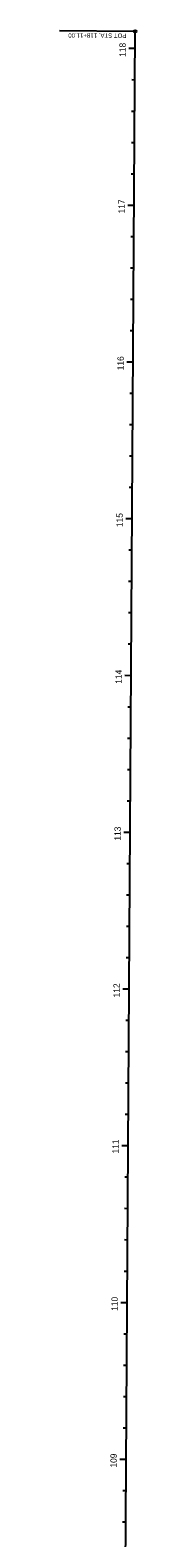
# Model space of a CAD drawing. Extents: x 509738 to 512118, y 1314883 to 1316817.
# Drawn here: x 510443 to 510492, y 1315855 to 1316817 of the extents above; entities that cross this region are included whole.
import ezdxf

# ---------------------------------------------------------------- set-up
doc = ezdxf.new("R2010")
doc.units = 0
for name, color, linetype in [('CLConst_dp', 7, 'Continuous'), ('CurveDataLabel_dp', 7, 'Continuous'), ('StationTicL_dp', 7, 'Continuous'), ('StationTicS_dp', 7, 'Continuous'), ('TextBLStation', 7, 'Continuous')]:
    doc.layers.add(name, color=color, linetype=linetype)

msp = doc.modelspace()

# ---------------------------------------------------------------- linework, layer by layer
at = {"layer": 'CLConst_dp'}
msp.add_line((510484.13, 1315694.91), (510491.26, 1316815.91), dxfattribs=at)
at = {"layer": 'CurveDataLabel_dp'}
msp.add_line((510490.46, 1316815.91), (510442.98, 1316816.21), dxfattribs=at)
msp.add_circle((510491.26, 1316815.91), 0.8, dxfattribs=at)
at = {"layer": 'StationTicL_dp'}
for p, q in [((510491.19, 1316804.91), (510487.19, 1316804.93)), ((510490.56, 1316704.91), (510486.56, 1316704.94)), ((510489.92, 1316604.91), (510485.92, 1316604.94)), ((510489.29, 1316504.91), (510485.29, 1316504.94)), ((510488.65, 1316404.92), (510484.65, 1316404.94)), ((510488.01, 1316304.92), (510484.01, 1316304.94)), ((510487.38, 1316204.92), (510483.38, 1316204.95)), ((510486.74, 1316104.92), (510482.74, 1316104.95)), ((510486.11, 1316004.92), (510482.11, 1316004.95)), ((510485.47, 1315904.93), (510481.47, 1315904.95))]:
    msp.add_line(p, q, dxfattribs=at)
at = {"layer": 'StationTicS_dp'}
for p, q in [((510491.07, 1316784.91), (510489.07, 1316784.92)), ((510490.94, 1316764.91), (510488.94, 1316764.92)), ((510490.81, 1316744.91), (510488.81, 1316744.92)), ((510490.68, 1316724.91), (510488.68, 1316724.92)), ((510490.43, 1316684.91), (510488.43, 1316684.92)), ((510490.3, 1316664.91), (510488.3, 1316664.92)), ((510490.18, 1316644.91), (510488.18, 1316644.92)), ((510490.05, 1316624.91), (510488.05, 1316624.92)), ((510489.79, 1316584.91), (510487.79, 1316584.92)), ((510489.67, 1316564.91), (510487.67, 1316564.93)), ((510489.54, 1316544.91), (510487.54, 1316544.93)), ((510489.41, 1316524.91), (510487.41, 1316524.93)), ((510489.16, 1316484.91), (510487.16, 1316484.93)), ((510489.03, 1316464.91), (510487.03, 1316464.93)), ((510488.9, 1316444.92), (510486.9, 1316444.93)), ((510488.78, 1316424.92), (510486.78, 1316424.93)), ((510488.52, 1316384.92), (510486.52, 1316384.93)), ((510488.4, 1316364.92), (510486.4, 1316364.93)), ((510488.27, 1316344.92), (510486.27, 1316344.93)), ((510488.14, 1316324.92), (510486.14, 1316324.93)), ((510487.89, 1316284.92), (510485.89, 1316284.93)), ((510487.76, 1316264.92), (510485.76, 1316264.93)), ((510487.63, 1316244.92), (510485.63, 1316244.93)), ((510487.51, 1316224.92), (510485.51, 1316224.93)), ((510487.25, 1316184.92), (510485.25, 1316184.93)), ((510487.12, 1316164.92), (510485.12, 1316164.93)), ((510487, 1316144.92), (510485, 1316144.93)), ((510486.87, 1316124.92), (510484.87, 1316124.93)), ((510486.61, 1316084.92), (510484.61, 1316084.94)), ((510486.49, 1316064.92), (510484.49, 1316064.94)), ((510486.36, 1316044.92), (510484.36, 1316044.94)), ((510486.23, 1316024.92), (510484.23, 1316024.94)), ((510485.98, 1315984.92), (510483.98, 1315984.94)), ((510485.85, 1315964.92), (510483.85, 1315964.94)), ((510485.72, 1315944.93), (510483.72, 1315944.94)), ((510485.6, 1315924.93), (510483.6, 1315924.94)), ((510485.34, 1315884.93), (510483.34, 1315884.94)), ((510485.22, 1315864.93), (510483.22, 1315864.94))]:
    msp.add_line(p, q, dxfattribs=at)

# ---------------------------------------------------------------- texts
at = {"layer": 'CurveDataLabel_dp'}
msp.add_text('POT STA. 118+11.00', height=2.8, rotation=179.63561, dxfattribs=at).set_placement((510485.65, 1316814.54))
at = {"layer": 'TextBLStation'}
for s, p in [('118', (510485.16, 1316799.69)), ('117', (510484.52, 1316699.77)), ('116', (510483.89, 1316599.72)), ('115', (510483.25, 1316499.7)), ('114', (510482.62, 1316399.76)), ('113', (510481.98, 1316299.68)), ('112', (510481.34, 1316199.69)), ('111', (510480.71, 1316100.05)), ('110', (510480.07, 1315999.74)), ('109', (510479.44, 1315899.74))]:
    msp.add_text(s, height=4, rotation=89.63561, dxfattribs=at).set_placement(p)

doc.saveas('drawing.dxf')
